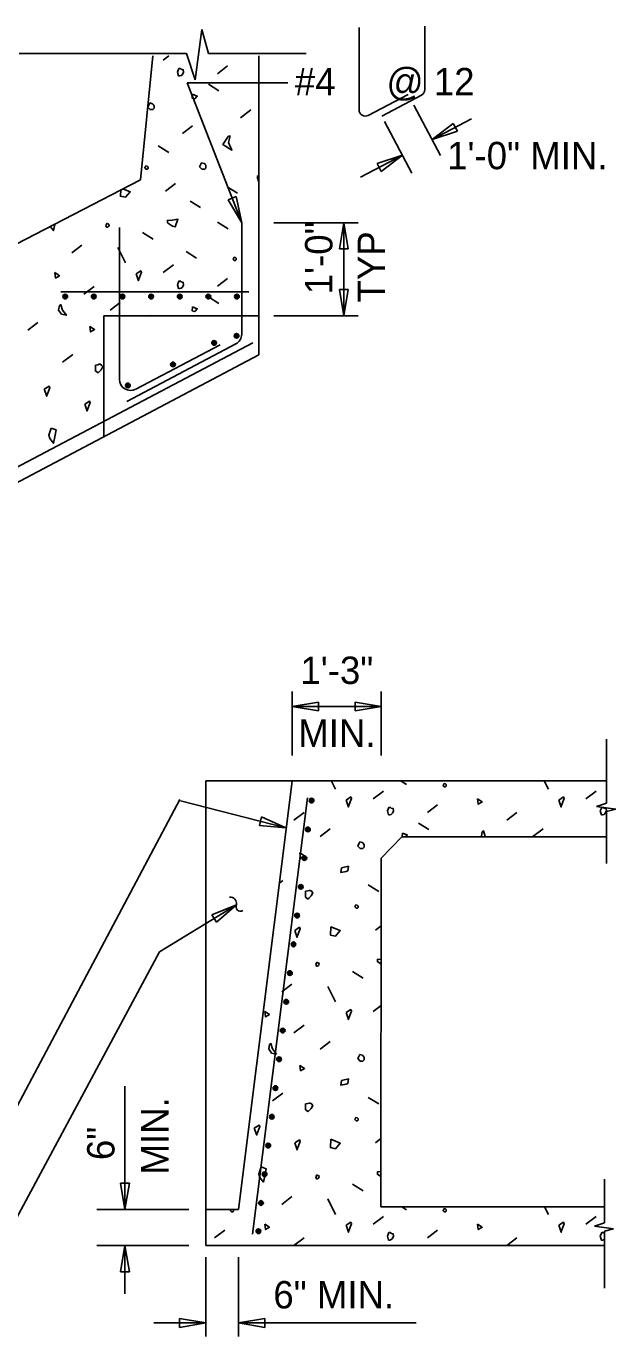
# Model space of a CAD drawing. Extents: x 0 to 22.7, y 0 to 15.7.
# Drawn here: x 6.629 to 8.87, y 5.449 to 10.444 of the extents above; entities that cross this region are included whole.
import ezdxf

# ---------------------------------------------------------------- set-up
doc = ezdxf.new("R2010")
doc.units = 0
for name, color, linetype in [('BRDG_ANNO_General-Notes', 7, 'Continuous'), ('BRDG_BASE_Obj-Line', 7, 'Continuous'), ('BRDG_BASE_Pattern', 7, 'Continuous'), ('BRDG_BASE_Rebar', 7, 'Continuous')]:
    doc.layers.add(name, color=color, linetype=linetype)

msp = doc.modelspace()

# ---------------------------------------------------------------- linework, layer by layer
at = {"layer": 'BRDG_ANNO_General-Notes'}
for p, q in [((7.6241, 10.2291), (7.2413, 10.2291)), ((7.2413, 10.2291), (7.4482, 9.6979)), ((8.1028, 10.1447), (8.2035, 9.953)), ((8.3223, 10.0925), (8.1718, 10.0134)), ((7.9913, 10.0827), (8.0948, 9.8856)), ((8.1718, 10.0134), (8.2526, 10.0747)), ((8.2681, 10.0452), (8.1718, 10.0134)), ((8.2526, 10.0747), (8.2681, 10.0452)), ((8.0589, 9.9542), (7.8994, 9.8704)), ((7.9626, 9.9224), (8.0589, 9.9542)), ((8.0589, 9.9542), (7.9781, 9.8929)), ((7.9781, 9.8929), (7.9626, 9.9224)), ((7.3964, 9.7851), (7.4274, 9.7971)), ((7.4274, 9.7971), (7.4482, 9.6979)), ((7.4482, 9.6979), (7.3964, 9.7851)), ((7.8906, 9.6979), (7.5698, 9.6979)), ((7.8196, 9.5979), (7.8363, 9.6979)), ((7.8363, 9.344), (7.8363, 9.6979)), ((7.8363, 9.6979), (7.853, 9.5979)), ((7.853, 9.5979), (7.8196, 9.5979)), ((7.8196, 9.444), (7.853, 9.444)), ((7.8363, 9.344), (7.8196, 9.444)), ((7.853, 9.444), (7.8363, 9.344)), ((7.8906, 9.344), (7.5698, 9.344)), ((7.6405, 7.916), (7.6405, 7.6733)), ((7.9789, 7.916), (7.9789, 7.6733)), ((7.6405, 7.8597), (7.7405, 7.8764)), ((7.6405, 7.8597), (7.9789, 7.8597)), ((7.7405, 7.8431), (7.6405, 7.8597)), ((7.7405, 7.8764), (7.7405, 7.8431)), ((7.8789, 7.8431), (7.8789, 7.8764)), ((7.8789, 7.8764), (7.9789, 7.8597)), ((7.9789, 7.8597), (7.8789, 7.8431)), ((6.3616, 5.9025), (7.2128, 7.5057)), ((7.2149, 7.5006), (7.6165, 7.3987)), ((7.5154, 7.4071), (7.5236, 7.4395)), ((7.6165, 7.3987), (7.5154, 7.4071)), ((7.5236, 7.4395), (7.6165, 7.3987)), ((7.4286, 7.1061), (7.1358, 6.9271)), ((7.1358, 6.9271), (7.4286, 7.1061)), ((7.3346, 7.0682), (7.4286, 7.1061)), ((7.4286, 7.1061), (7.352, 7.0397)), ((7.352, 7.0397), (7.3346, 7.0682)), ((6.3306, 5.43), (7.1358, 6.9271)), ((7.0045, 6.4164), (7.0045, 5.9486)), ((6.9878, 6.0486), (7.0211, 6.0486)), ((7.0045, 5.9486), (6.9878, 6.0486)), ((7.0211, 6.0486), (7.0045, 5.9486)), ((7.2478, 5.9486), (6.8968, 5.9486)), ((7.2478, 5.811), (6.8968, 5.811)), ((6.9878, 5.711), (7.0045, 5.811)), ((7.0045, 5.811), (7.0045, 5.6279)), ((7.0045, 5.811), (7.0211, 5.711)), ((7.3117, 5.7664), (7.3117, 5.4657)), ((7.4355, 5.7664), (7.4355, 5.4657)), ((7.0211, 5.711), (6.9878, 5.711)), ((7.3117, 5.5168), (7.1144, 5.5168)), ((7.2117, 5.5002), (7.2117, 5.5335)), ((7.2117, 5.5335), (7.3117, 5.5168)), ((7.3117, 5.5168), (7.2117, 5.5002)), ((7.4355, 5.5168), (7.5355, 5.5335)), ((8.1115, 5.5168), (7.4355, 5.5168)), ((7.5355, 5.5002), (7.4355, 5.5168)), ((7.5355, 5.5335), (7.5355, 5.5002))]:
    msp.add_line(p, q, dxfattribs=at)
for centre, radius, start, end in [((7.4031, 7.1094), 0.0257, 352.6754, 92.3829), ((7.4433, 7.098), 0.0168, 151.1229, 301.9945)]:
    msp.add_arc(centre, radius, start, end, dxfattribs=at)
at = {"layer": 'BRDG_BASE_Obj-Line'}
for p, q in [((7.2711, 10.2406), (7.2966, 10.4317)), ((7.2966, 10.4317), (7.3223, 10.3412)), ((7.2386, 10.3412), (6.6021, 10.3412)), ((7.2386, 10.3412), (7.2711, 10.2406)), ((7.693, 10.3412), (7.3223, 10.3412)), ((7.1107, 10.332), (7.0631, 9.8613)), ((7.5139, 9.1952), (7.5139, 10.332)), ((7.0631, 9.8613), (6.1473, 9.3866)), ((6.924, 8.8871), (6.924, 9.344)), ((6.924, 9.344), (7.5139, 9.344)), ((6.144, 8.4744), (7.5139, 9.1952)), ((8.8355, 7.4919), (8.8355, 7.7355)), ((7.3117, 5.811), (7.3117, 7.5766)), ((7.3117, 7.5766), (8.8355, 7.5766)), ((7.6405, 7.5757), (7.4355, 5.9486)), ((8.8355, 7.4919), (8.7969, 7.4793)), ((8.7969, 7.4793), (8.8701, 7.4697)), ((8.8701, 7.4697), (8.8355, 7.4598)), ((8.8355, 7.2633), (8.8355, 7.4598)), ((8.0574, 7.3645), (7.9789, 7.2828)), ((8.0574, 7.3645), (8.8355, 7.3646)), ((7.9789, 7.2828), (7.9767, 5.9583)), ((8.8277, 5.8972), (8.8277, 6.0632)), ((7.3117, 5.9486), (7.4355, 5.9486)), ((7.9767, 5.9583), (8.8277, 5.9583)), ((8.8277, 5.8972), (8.7891, 5.8847)), ((8.7891, 5.8847), (8.8622, 5.8751)), ((8.8622, 5.8751), (8.8277, 5.8652)), ((8.8277, 5.649), (8.8277, 5.8652)), ((7.3117, 5.811), (8.8273, 5.811))]:
    msp.add_line(p, q, dxfattribs=at)
at = {"layer": 'BRDG_BASE_Pattern'}
for p, q in [((7.1707, 10.332), (7.1498, 10.316)), ((7.3941, 10.2934), (7.3556, 10.2641)), ((7.3221, 10.2241), (7.3617, 10.1991)), ((7.4823, 10.1261), (7.4439, 10.0968)), ((7.2614, 10.0664), (7.2229, 10.0371)), ((7.131, 9.9895), (7.1706, 9.9645)), ((7.1966, 9.8466), (7.158, 9.8173)), ((7.3926, 9.8346), (7.4321, 9.8098)), ((7.2517, 9.78), (7.2913, 9.755)), ((7.3566, 9.6994), (7.3961, 9.6744)), ((7.0716, 9.6602), (7.1111, 9.6352)), ((6.8403, 9.6124), (6.8018, 9.5831)), ((6.9776, 9.6035), (7.0069, 9.5447)), ((7.2367, 9.5879), (7.2763, 9.5629)), ((7.1883, 9.5374), (7.1498, 9.5081)), ((6.887, 9.4559), (6.8485, 9.4266)), ((7.3941, 9.4854), (7.3556, 9.4561)), ((6.9864, 9.3946), (6.9479, 9.3653)), ((7.3221, 9.4161), (7.3617, 9.3911)), ((6.6735, 9.3182), (6.6351, 9.2889)), ((6.8056, 9.1972), (6.7671, 9.1679)), ((7.7899, 7.5758), (7.8053, 7.5451)), ((8.0544, 7.576), (8.0746, 7.5632)), ((8.5984, 7.5765), (8.6141, 7.5451)), ((7.9867, 7.5377), (7.9482, 7.5084)), ((8.7955, 7.5377), (8.757, 7.5084)), ((7.6854, 7.4562), (7.6469, 7.4269)), ((8.1924, 7.4857), (8.154, 7.4565)), ((8.4942, 7.4562), (8.4557, 7.4269)), ((7.7848, 7.3949), (7.7463, 7.3657)), ((8.1205, 7.4165), (8.1601, 7.3915)), ((8.5936, 7.3949), (8.5551, 7.3657)), ((7.604, 7.1976), (7.5917, 7.1882)), ((7.9294, 7.1818), (7.969, 7.1569)), ((7.9784, 7.0264), (7.9564, 7.0096)), ((7.8699, 6.8525), (7.9095, 6.8275)), ((7.6387, 6.8048), (7.6002, 6.7755)), ((7.776, 6.7959), (7.8053, 6.7371)), ((7.9779, 6.7231), (7.9482, 6.7005)), ((7.6854, 6.6482), (7.6469, 6.619)), ((7.7848, 6.587), (7.7463, 6.5577)), ((7.604, 6.3896), (7.5655, 6.3603)), ((7.9294, 6.3739), (7.969, 6.3489)), ((7.9771, 6.2174), (7.9564, 6.2017)), ((7.8699, 6.0445), (7.9095, 6.0195)), ((7.6387, 5.9968), (7.6002, 5.9676)), ((7.776, 5.988), (7.8053, 5.9291)), ((8.0573, 5.9583), (8.0746, 5.9473)), ((8.5995, 5.9583), (8.6141, 5.9291)), ((7.9867, 5.9218), (7.9482, 5.8925)), ((8.7955, 5.9218), (8.757, 5.8925)), ((7.3836, 5.8698), (7.3452, 5.8405)), ((8.1924, 5.8698), (8.154, 5.8405)), ((7.6854, 5.8403), (7.6469, 5.811)), ((8.4942, 5.8403), (8.4557, 5.811))]:
    msp.add_line(p, q, dxfattribs=at)
for points in [[(7.2037, 10.2703), (7.2083, 10.2555), (7.2126, 10.2555), (7.2186, 10.257), (7.2229, 10.2613), (7.2272, 10.2703), (7.226, 10.2791), (7.2186, 10.2806), (7.2155, 10.2836), (7.2096, 10.2836)], [(7.0987, 10.1529), (7.0913, 10.1368), (7.0999, 10.1278), (7.1105, 10.1278), (7.1149, 10.1325), (7.1149, 10.1411), (7.1134, 10.1454), (7.1089, 10.1501)], [(7.261, 10.1862), (7.2604, 10.1704), (7.2699, 10.1682), (7.2791, 10.1789)], [(7.397, 10.0255), (7.3765, 9.9947), (7.4111, 9.974), (7.3984, 10.002), (7.4037, 10.0277)], [(7.084, 9.9134), (7.0803, 9.9054), (7.0846, 9.9008), (7.0899, 9.9008), (7.092, 9.9032), (7.092, 9.9075), (7.0913, 9.9097), (7.089, 9.912)], [(7.2955, 9.9259), (7.2881, 9.9098), (7.2968, 9.9008), (7.3074, 9.9008), (7.3117, 9.9055), (7.3117, 9.9141), (7.3103, 9.9184), (7.3057, 9.9231)], [(6.932, 9.6876), (6.9343, 9.6802), (6.9365, 9.6802), (6.9394, 9.6809), (6.9416, 9.683), (6.9437, 9.6876), (6.9431, 9.6919), (6.9394, 9.6927), (6.9379, 9.6942), (6.9349, 9.6942)], [(7.1834, 9.7078), (7.1657, 9.7062), (7.1657, 9.6974), (7.1849, 9.6842), (7.1953, 9.6827), (7.2056, 9.7107)], [(7.4192, 9.567), (7.4155, 9.5589), (7.4198, 9.5544), (7.4252, 9.5544), (7.4273, 9.5568), (7.4273, 9.5611), (7.4266, 9.5632), (7.4243, 9.5656)], [(6.7376, 9.508), (6.7405, 9.4873), (6.7553, 9.4962)], [(7.0464, 9.5037), (7.0555, 9.4771), (7.0555, 9.48), (7.0673, 9.5096), (7.0643, 9.5155)], [(7.2037, 9.4623), (7.2083, 9.4476), (7.2126, 9.4476), (7.2186, 9.4491), (7.2229, 9.4533), (7.2272, 9.4623), (7.226, 9.4711), (7.2186, 9.4726), (7.2155, 9.4757), (7.2096, 9.4757)], [(6.7555, 9.3827), (6.7523, 9.366), (6.7633, 9.3498), (6.7817, 9.3462), (6.767, 9.3657), (6.7607, 9.3859)], [(7.261, 9.3783), (7.2604, 9.3624), (7.2699, 9.3602), (7.2791, 9.3709)], [(6.8708, 9.3034), (6.8739, 9.2828), (6.8886, 9.2917)], [(6.8921, 9.157), (6.8921, 9.1347), (6.9022, 9.1275), (6.9053, 9.1304), (6.914, 9.1393), (6.9199, 9.1511), (6.9156, 9.157), (6.9097, 9.1598), (6.9068, 9.1598), (6.901, 9.1582)], [(6.6978, 9.0648), (6.7069, 9.0383), (6.7069, 9.0411), (6.7187, 9.0707), (6.7157, 9.0766)], [(6.8515, 9.0083), (6.8606, 8.9817), (6.8606, 8.9846), (6.8724, 9.0142), (6.8694, 9.0201)], [(6.7236, 8.9174), (6.7147, 8.8908), (6.7193, 8.8776), (6.7325, 8.8599), (6.7383, 8.8835), (6.7428, 8.9101)], [(8.2176, 7.5673), (8.2139, 7.5592), (8.2182, 7.5547), (8.2235, 7.5547), (8.2257, 7.5571), (8.2257, 7.5614), (8.225, 7.5635), (8.2227, 7.5659)], [(7.8448, 7.504), (7.8539, 7.4774), (7.8539, 7.4803), (7.8657, 7.5099), (7.8627, 7.5158)], [(8.3447, 7.5083), (8.3477, 7.4877), (8.3625, 7.4966)], [(8.6536, 7.504), (8.6627, 7.4774), (8.6627, 7.4803), (8.6745, 7.5099), (8.6715, 7.5158)], [(8.0021, 7.4627), (8.0067, 7.4479), (8.011, 7.4479), (8.017, 7.4494), (8.0213, 7.4536), (8.0256, 7.4627), (8.0244, 7.4714), (8.017, 7.473), (8.0139, 7.476), (8.008, 7.476)], [(8.8109, 7.4627), (8.8155, 7.4479), (8.8198, 7.4479), (8.8258, 7.4494), (8.8301, 7.4536), (8.8344, 7.4627), (8.8332, 7.4714), (8.8258, 7.473), (8.8227, 7.476), (8.8168, 7.476)], [(7.8971, 7.3453), (7.8897, 7.3291), (7.8983, 7.3202), (7.9089, 7.3202), (7.9133, 7.3248), (7.9133, 7.3335), (7.9118, 7.3377), (7.9072, 7.3424)], [(7.6692, 7.3037), (7.6722, 7.2831), (7.687, 7.292)], [(7.8275, 7.2465), (7.8245, 7.2288), (7.8452, 7.2318), (7.851, 7.2346), (7.854, 7.2523)], [(7.6905, 7.1573), (7.6905, 7.135), (7.7006, 7.1278), (7.7037, 7.1307), (7.7124, 7.1396), (7.7183, 7.1514), (7.714, 7.1573), (7.7081, 7.1602), (7.7052, 7.1602), (7.6994, 7.1585)], [(7.8823, 7.1058), (7.8786, 7.0977), (7.883, 7.0932), (7.8883, 7.0932), (7.8904, 7.0956), (7.8904, 7.0999), (7.8897, 7.102), (7.8874, 7.1044)], [(7.6499, 7.0086), (7.659, 6.982), (7.659, 6.9849), (7.6708, 7.0145), (7.6678, 7.0204)], [(7.787, 7.0227), (7.7856, 6.991), (7.8047, 6.9866), (7.8231, 7.0079)], [(7.7304, 6.8799), (7.7327, 6.8725), (7.7348, 6.8725), (7.7378, 6.8733), (7.74, 6.8754), (7.7421, 6.8799), (7.7415, 6.8843), (7.7378, 6.8851), (7.7363, 6.8866), (7.7333, 6.8866)], [(7.5359, 6.7004), (7.5389, 6.6797), (7.5537, 6.6886)], [(7.8448, 6.6961), (7.8539, 6.6695), (7.8539, 6.6723), (7.8657, 6.7019), (7.8627, 6.7078)], [(7.5539, 6.5751), (7.5507, 6.5584), (7.5617, 6.5422), (7.5801, 6.5385), (7.5654, 6.5581), (7.5591, 6.5783)], [(7.6692, 6.4958), (7.6722, 6.4752), (7.687, 6.484)], [(7.8971, 6.5373), (7.8897, 6.5212), (7.8983, 6.5122), (7.9089, 6.5122), (7.9133, 6.5169), (7.9133, 6.5255), (7.9118, 6.5297), (7.9072, 6.5345)], [(7.8275, 6.4385), (7.8245, 6.4208), (7.8452, 6.4238), (7.851, 6.4267), (7.854, 6.4444)], [(7.6905, 6.3494), (7.6905, 6.327), (7.7006, 6.3198), (7.7037, 6.3228), (7.7124, 6.3316), (7.7183, 6.3434), (7.714, 6.3494), (7.7081, 6.3522), (7.7052, 6.3522), (7.6994, 6.3506)], [(7.8823, 6.2979), (7.8786, 6.2897), (7.883, 6.2853), (7.8883, 6.2853), (7.8904, 6.2876), (7.8904, 6.2919), (7.8897, 6.2941), (7.8874, 6.2964)], [(7.4961, 6.2572), (7.5053, 6.2306), (7.5053, 6.2335), (7.5171, 6.2631), (7.5141, 6.269)], [(7.6499, 6.2007), (7.659, 6.1741), (7.659, 6.1769), (7.6708, 6.2066), (7.6678, 6.2124)], [(7.787, 6.2147), (7.7856, 6.1831), (7.8047, 6.1786), (7.8231, 6.1999)], [(7.522, 6.1097), (7.5131, 6.0832), (7.5177, 6.0699), (7.5309, 6.0522), (7.5367, 6.0758), (7.5412, 6.1024)], [(7.7304, 6.0719), (7.7327, 6.0645), (7.7348, 6.0645), (7.7378, 6.0653), (7.74, 6.0674), (7.7421, 6.0719), (7.7415, 6.0764), (7.7378, 6.0771), (7.7363, 6.0786), (7.7333, 6.0786)], [(8.2176, 5.9514), (8.2139, 5.9433), (8.2182, 5.9388), (8.2235, 5.9388), (8.2257, 5.9412), (8.2257, 5.9455), (8.225, 5.9477), (8.2227, 5.95)], [(7.8448, 5.8881), (7.8539, 5.8615), (7.8539, 5.8644), (7.8657, 5.894), (7.8627, 5.8998)], [(8.6536, 5.8881), (8.6627, 5.8615), (8.6627, 5.8644), (8.6745, 5.894), (8.6715, 5.8998)], [(7.5359, 5.8924), (7.5389, 5.8718), (7.5537, 5.8807)], [(8.0021, 5.8467), (8.0067, 5.832), (8.011, 5.832), (8.017, 5.8334), (8.0213, 5.8378), (8.0256, 5.8467), (8.0244, 5.8555), (8.017, 5.857), (8.0139, 5.8601), (8.008, 5.8601)], [(8.3447, 5.8924), (8.3477, 5.8718), (8.3625, 5.8807)]]:
    msp.add_lwpolyline(points, close=True, dxfattribs=at)
for points in [[(7.5139, 9.8776), (7.5066, 9.8728)], [(7.5066, 9.8728), (7.5139, 9.8516)], [(6.9882, 9.8225), (6.9872, 9.7986), (7.0063, 9.7942), (7.0247, 9.8156), (6.9968, 9.827)], [(6.7206, 9.6838), (6.7325, 9.6679), (6.7383, 9.6915), (6.7386, 9.6931)], [(7.0987, 9.345), (7.0982, 9.344)], [(7.1024, 9.344), (7.0987, 9.345)], [(8.0594, 7.3786), (8.0588, 7.3645)], [(8.0717, 7.3645), (8.0775, 7.3712), (8.0594, 7.3786)], [(8.3627, 7.383), (8.3594, 7.3664), (8.3607, 7.3645)], [(8.3753, 7.3645), (8.3742, 7.366), (8.3679, 7.3863), (8.3627, 7.383)], [(7.9782, 6.8998), (7.9641, 6.8986), (7.9641, 6.8898), (7.9782, 6.8801)], [(7.9769, 6.0918), (7.9641, 6.0907), (7.9641, 6.0819), (7.9769, 6.0731)], [(7.4075, 5.9486), (7.4051, 5.9433), (7.4094, 5.9388), (7.4147, 5.9388), (7.4169, 5.9412), (7.4169, 5.9455), (7.4162, 5.9477), (7.4153, 5.9486)], [(8.8274, 5.8567), (8.8258, 5.857), (8.8227, 5.8601), (8.8168, 5.8601), (8.8109, 5.8467)], [(8.8109, 5.8467), (8.8155, 5.832), (8.8198, 5.832), (8.8258, 5.8334), (8.8274, 5.8351)]]:
    msp.add_lwpolyline(points, dxfattribs=at)
at = {"layer": 'BRDG_BASE_Rebar'}
for p, q in [((7.8944, 10.4394), (7.8944, 10.1265)), ((8.1441, 10.203), (8.1441, 10.4442)), ((8.0814, 10.1855), (7.9291, 10.1055)), ((7.9808, 10.1028), (8.1316, 10.182)), ((7.4482, 9.274), (7.4482, 9.6979)), ((6.984, 9.679), (6.984, 9.1022)), ((6.7609, 9.4348), (7.475, 9.4348)), ((6.1497, 8.5355), (7.4903, 9.2409)), ((7.0109, 9.0187), (7.4259, 9.2371)), ((7.0451, 9.0653), (7.3662, 9.2343)), ((7.6978, 7.5125), (7.489, 5.8548))]:
    msp.add_line(p, q, dxfattribs=at)
for centre, radius in [((6.7771, 9.4173), 0.0089), ((6.7771, 9.4173), 0.00593), ((6.7771, 9.4173), 0.00297), ((6.8859, 9.4173), 0.0089), ((6.8859, 9.4173), 0.00593), ((6.8859, 9.4173), 0.00297), ((6.9948, 9.4173), 0.0089), ((6.9948, 9.4173), 0.00593), ((6.9948, 9.4173), 0.00297), ((7.1036, 9.4173), 0.0089), ((7.1036, 9.4173), 0.00593), ((7.1036, 9.4173), 0.00297), ((7.2125, 9.4173), 0.0089), ((7.2125, 9.4173), 0.00593), ((7.2125, 9.4173), 0.00297), ((7.3213, 9.4173), 0.0089), ((7.3213, 9.4173), 0.00593), ((7.3213, 9.4173), 0.00297), ((7.4302, 9.4173), 0.0089), ((7.4302, 9.4173), 0.00593), ((7.4302, 9.4173), 0.00297), ((7.3431, 9.2412), 0.0089), ((7.3431, 9.2412), 0.00593), ((7.3431, 9.2412), 0.00297), ((7.4288, 9.2679), 0.0089), ((7.4288, 9.2679), 0.00593), ((7.4288, 9.2679), 0.00297), ((7.187, 9.1594), 0.0089), ((7.187, 9.1594), 0.00593), ((7.187, 9.1594), 0.00297), ((7.0156, 9.0794), 0.0089), ((7.0156, 9.0794), 0.00593), ((7.0156, 9.0794), 0.00297), ((7.7138, 7.5017), 0.0089), ((7.7138, 7.5017), 0.00593), ((7.7138, 7.5017), 0.00297), ((7.7, 7.3925), 0.0089), ((7.7, 7.3925), 0.00593), ((7.7, 7.3925), 0.00297), ((7.6863, 7.2833), 0.0089), ((7.6863, 7.2833), 0.00593), ((7.6863, 7.2833), 0.00297), ((7.6725, 7.1741), 0.0089), ((7.6725, 7.1741), 0.00593), ((7.6725, 7.1741), 0.00297), ((7.6588, 7.0648), 0.0089), ((7.6588, 7.0648), 0.00593), ((7.6588, 7.0648), 0.00297), ((7.6451, 6.9556), 0.0089), ((7.6451, 6.9556), 0.00593), ((7.6451, 6.9556), 0.00297), ((7.6313, 6.8464), 0.0089), ((7.6313, 6.8464), 0.00593), ((7.6313, 6.8464), 0.00297), ((7.6176, 6.7372), 0.0089), ((7.6176, 6.7372), 0.00593), ((7.6176, 6.7372), 0.00297), ((7.6039, 6.628), 0.0089), ((7.6039, 6.628), 0.00593), ((7.6039, 6.628), 0.00297), ((7.5901, 6.5188), 0.0089), ((7.5901, 6.5188), 0.00593), ((7.5901, 6.5188), 0.00297), ((7.5764, 6.4096), 0.0089), ((7.5764, 6.4096), 0.00593), ((7.5764, 6.4096), 0.00297), ((7.5627, 6.3004), 0.0089), ((7.5627, 6.3004), 0.00593), ((7.5627, 6.3004), 0.00297), ((7.5489, 6.1911), 0.0089), ((7.5489, 6.1911), 0.00593), ((7.5489, 6.1911), 0.00297), ((7.5352, 6.0819), 0.0089), ((7.5352, 6.0819), 0.00593), ((7.5352, 6.0819), 0.00297), ((7.5215, 5.9727), 0.0089), ((7.5215, 5.9727), 0.00593), ((7.5215, 5.9727), 0.00297), ((7.5115, 5.8656), 0.0089), ((7.5115, 5.8656), 0.00593), ((7.5115, 5.8656), 0.00297)]:
    msp.add_circle(centre, radius, dxfattribs=at)
for centre, radius, start, end in [((8.1204, 10.203), 0.0237, 297.7533, 0), ((7.9181, 10.1265), 0.0237, 180, 297.7519), ((7.9181, 10.1265), 0.0237, 180, 297.7519), ((7.4065, 9.274), 0.0417, 297.7533, 0), ((7.0256, 9.1022), 0.0417, 180, 297.7519)]:
    msp.add_arc(centre, radius, start, end, dxfattribs=at)

# ---------------------------------------------------------------- texts
at = {"layer": 'BRDG_ANNO_General-Notes'}
for s, height, p in [('#4     @ 12', 0.104115, (7.6503, 10.1818)), ('1\'-0" MIN.', 0.10411, (8.2291, 9.9009)), ('1\'-3"', 0.10411, (7.6712, 7.9449)), ('MIN.', 0.10411, (7.6631, 7.706)), ('6" MIN.', 0.10411, (7.5684, 5.5721))]:
    msp.add_text(s, height=height, dxfattribs=at).set_placement(p)
for s, height, p in [('1\'-0"', 0.10417, (7.7931, 9.4255)), ('TYP', 0.10417, (7.9932, 9.3945)), ('MIN.', 0.10411, (7.1699, 6.0808)), ('6"', 0.10411, (6.9646, 6.1356))]:
    msp.add_text(s, height=height, rotation=90, dxfattribs=at).set_placement(p)

doc.saveas('drawing.dxf')
